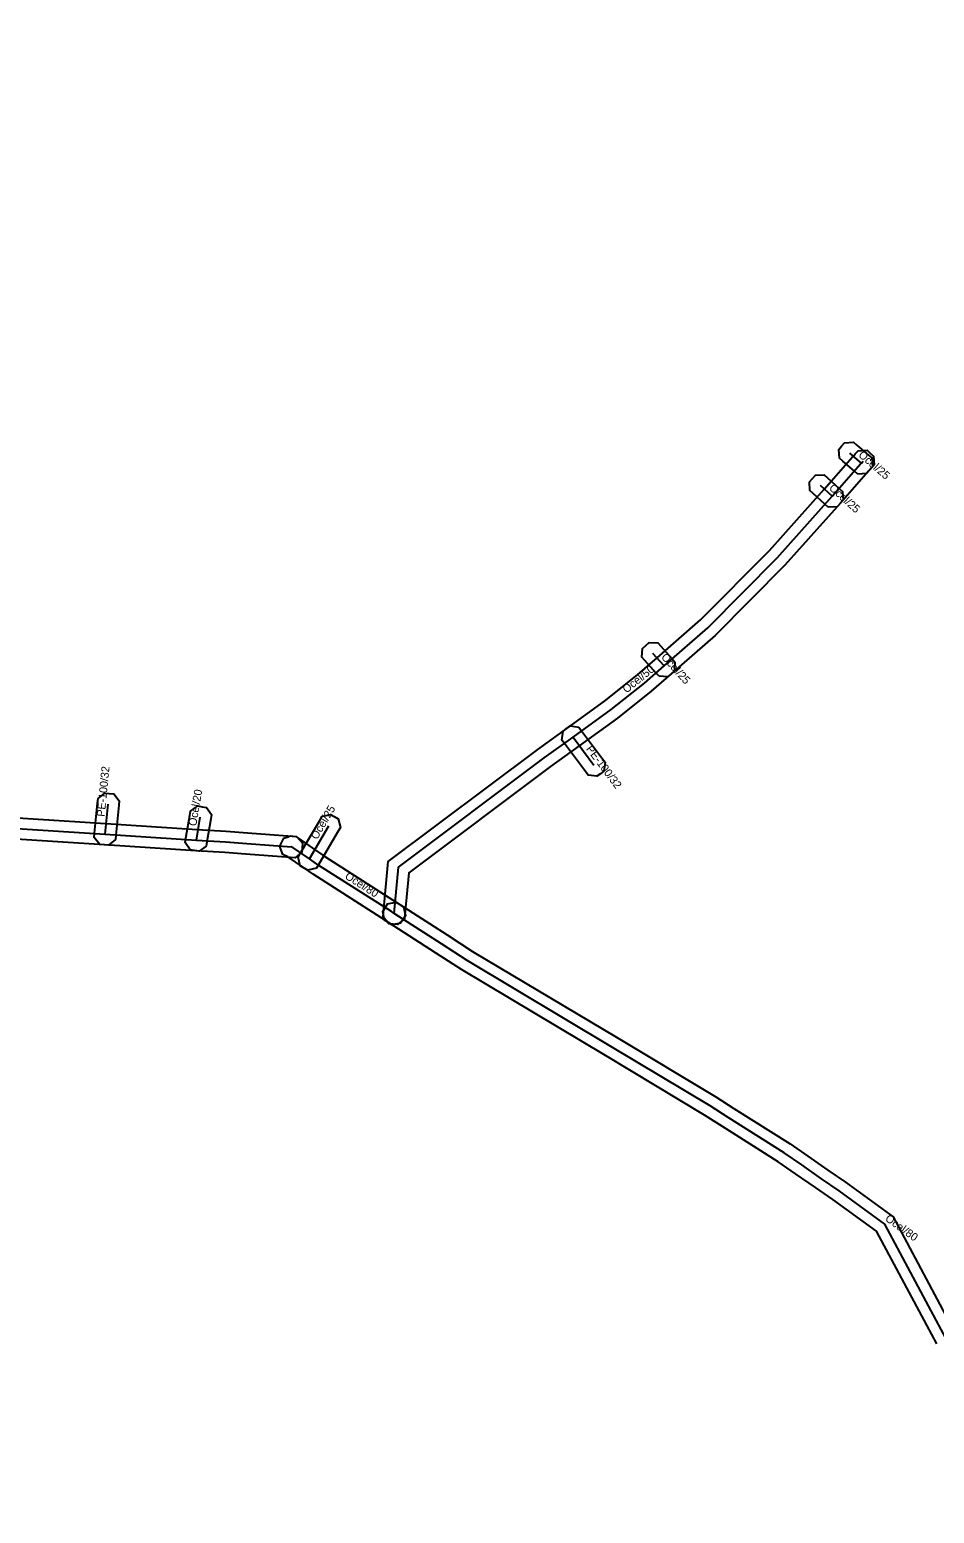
# Model space of a CAD drawing. Extents: x -569373 to -565022, y -1135090 to -1131496.
# Drawn here: x -565532.3 to -565447.5, y -1133985.7 to -1133846.6 of the extents above; entities that cross this region are included whole.
import ezdxf

# ---------------------------------------------------------------- set-up
doc = ezdxf.new("R2010")
doc.units = 0
for name, color, linetype in [('1', 7, 'Continuous'), ('24', 7, 'Continuous'), ('30', 7, 'Continuous')]:
    doc.layers.add(name, color=color, linetype=linetype)

msp = doc.modelspace()

# ---------------------------------------------------------------- linework, layer by layer
at = {"layer": '1'}
for points in [[(-565454.709, -1133888.287), (-565455.023, -1133888.017), (-565456.113, -1133887.077), (-565456.427, -1133886.807), (-565456.487, -1133885.981), (-565456.217, -1133885.667), (-565455.947, -1133885.353), (-565455.121, -1133885.293), (-565454.807, -1133885.563), (-565453.717, -1133886.503), (-565453.403, -1133886.773), (-565453.343, -1133887.599), (-565453.613, -1133887.913), (-565453.883, -1133888.227)], [(-565499.175, -1133929.779), (-565499.136, -1133929.366), (-565498.684, -1133924.585), (-565484.663, -1133914.085), (-565481.967, -1133912.13), (-565478.425, -1133909.563), (-565475.331, -1133907.102), (-565473.509, -1133905.507), (-565469.445, -1133901.951), (-565462.988, -1133895.444), (-565457.857, -1133889.705), (-565457.17, -1133888.928), (-565455.192, -1133886.68), (-565455.119, -1133886.597), (-565454.945, -1133886.403), (-565454.669, -1133886.094), (-565453.842, -1133886.049), (-565453.533, -1133886.325), (-565453.224, -1133886.601), (-565453.179, -1133887.428), (-565453.455, -1133887.737), (-565453.621, -1133887.923), (-565453.688, -1133888), (-565455.67, -1133890.252), (-565456.363, -1133891.035), (-565461.532, -1133896.816), (-565468.075, -1133903.409), (-565472.191, -1133907.013), (-565474.049, -1133908.638), (-565477.215, -1133911.157), (-565480.793, -1133913.75), (-565483.477, -1133915.695), (-565496.776, -1133925.655), (-565497.144, -1133929.554), (-565497.183, -1133929.967), (-565497.821, -1133930.495), (-565498.234, -1133930.456), (-565498.647, -1133930.417)], [(-565457.476, -1133891.389), (-565457.783, -1133891.11), (-565458.883, -1133890.11), (-565459.19, -1133889.831), (-565459.229, -1133889.004), (-565458.95, -1133888.697), (-565458.671, -1133888.39), (-565457.844, -1133888.351), (-565457.537, -1133888.63), (-565456.437, -1133889.63), (-565456.13, -1133889.909), (-565456.091, -1133890.736), (-565456.37, -1133891.043), (-565456.649, -1133891.35)], [(-565473.317, -1133907.236), (-565473.594, -1133906.928), (-565474.644, -1133905.758), (-565474.921, -1133905.45), (-565474.876, -1133904.623), (-565474.568, -1133904.346), (-565474.26, -1133904.069), (-565473.433, -1133904.114), (-565473.156, -1133904.422), (-565472.106, -1133905.592), (-565471.829, -1133905.9), (-565471.874, -1133906.727), (-565472.182, -1133907.004), (-565472.49, -1133907.281)], [(-565480.827, -1133912.009), (-565480.579, -1133912.341), (-565478.619, -1133914.961), (-565478.371, -1133915.293), (-565478.489, -1133916.113), (-565478.821, -1133916.361), (-565479.153, -1133916.609), (-565479.973, -1133916.491), (-565480.221, -1133916.159), (-565482.181, -1133913.539), (-565482.429, -1133913.207), (-565482.311, -1133912.387), (-565481.979, -1133912.139), (-565481.647, -1133911.891)], [(-565526.236, -1133922.343), (-565526.195, -1133921.931), (-565525.915, -1133919.111), (-565525.874, -1133918.699), (-565525.233, -1133918.174), (-565524.821, -1133918.215), (-565524.409, -1133918.256), (-565523.884, -1133918.897), (-565523.925, -1133919.309), (-565524.205, -1133922.129), (-565524.246, -1133922.541), (-565524.887, -1133923.066), (-565525.299, -1133923.025), (-565525.711, -1133922.984)], [(-565517.715, -1133922.822), (-565517.646, -1133922.414), (-565517.286, -1133920.274), (-565517.217, -1133919.866), (-565516.542, -1133919.385), (-565516.134, -1133919.454), (-565515.726, -1133919.523), (-565515.245, -1133920.198), (-565515.314, -1133920.606), (-565515.674, -1133922.746), (-565515.743, -1133923.154), (-565516.418, -1133923.635), (-565516.826, -1133923.566), (-565517.234, -1133923.497)], [(-565507.142, -1133924.189), (-565506.932, -1133923.832), (-565505.112, -1133920.742), (-565504.902, -1133920.385), (-565504.099, -1133920.178), (-565503.742, -1133920.388), (-565503.385, -1133920.598), (-565503.178, -1133921.401), (-565503.388, -1133921.758), (-565505.208, -1133924.848), (-565505.418, -1133925.205), (-565506.221, -1133925.412), (-565506.578, -1133925.202), (-565506.935, -1133924.992)], [(-565506.637, -1133925.164), (-565508.1, -1133924.168), (-565508.578, -1133923.929), (-565508.709, -1133923.536), (-565508.84, -1133923.143), (-565508.469, -1133922.402), (-565508.076, -1133922.271), (-565508.046, -1133922.261), (-565507.824, -1133922.187), (-565507.361, -1133922.252), (-565507.167, -1133922.383), (-565505.503, -1133923.516), (-565504.625, -1133924.128), (-565497.857, -1133928.45), (-565497.593, -1133928.623), (-565497.246, -1133928.85), (-565497.076, -1133929.66), (-565497.303, -1133930.007), (-565497.53, -1133930.354), (-565498.34, -1133930.524), (-565498.687, -1133930.297), (-565498.943, -1133930.13), (-565505.735, -1133925.792)]]:
    msp.add_lwpolyline(points, close=True, dxfattribs=at)
for points in [[(-565534.394, -1133920.442), (-565525.136, -1133921.032), (-565516.597, -1133921.582), (-565513.861, -1133921.752), (-565511.864, -1133921.903), (-565507.684, -1133922.223), (-565507.271, -1133922.254), (-565506.732, -1133922.883), (-565506.763, -1133923.296), (-565506.794, -1133923.709), (-565507.423, -1133924.248), (-565507.836, -1133924.217), (-565512.016, -1133923.897), (-565513.999, -1133923.748), (-565516.723, -1133923.578), (-565525.264, -1133923.028), (-565534.506, -1133922.438)], [(-565447.317, -1133969.783), (-565448.252, -1133968.031), (-565452.954, -1133959.234), (-565457.029, -1133956.276), (-565458.661, -1133955.144), (-565460.528, -1133953.85), (-565462.153, -1133952.724), (-565467.375, -1133949.415), (-565469.055, -1133948.351), (-565478.344, -1133942.778), (-565491.837, -1133934.71), (-565494.257, -1133933.152), (-565498.682, -1133930.301), (-565499.03, -1133930.076), (-565499.205, -1133929.266), (-565498.981, -1133928.918), (-565498.756, -1133928.57), (-565497.946, -1133928.395), (-565497.598, -1133928.619), (-565493.173, -1133931.47), (-565490.783, -1133933.01), (-565477.316, -1133941.062), (-565468.005, -1133946.649), (-565466.305, -1133947.725), (-565461.047, -1133951.056), (-565459.388, -1133952.206), (-565457.521, -1133953.5), (-565455.871, -1133954.644), (-565451.406, -1133957.886), (-565446.488, -1133967.089)]]:
    msp.add_lwpolyline(points, dxfattribs=at)
at = {"layer": '24'}
for points in [[(-565579.49, -1133846.01), (-565580.85, -1133848.22), (-565588.2, -1133860.18), (-565592.04, -1133865.81), (-565595.63, -1133871.07), (-565584.05, -1133886.37), (-565583.94, -1133886.52), (-565582.13, -1133888.95), (-565569.79, -1133905.24), (-565569.78, -1133905.26), (-565568.53, -1133906.82), (-565568.34, -1133907.04), (-565564.3, -1133909.45), (-565562.562, -1133910.433), (-565555.42, -1133914.47), (-565549.74, -1133917.67), (-565539.06, -1133921.22), (-565536.45, -1133921.345), (-565534.45, -1133921.44), (-565525.2, -1133922.03), (-565516.66, -1133922.58), (-565513.93, -1133922.75), (-565511.94, -1133922.9), (-565507.76, -1133923.22)], [(-565454.37, -1133887.26), (-565455.46, -1133886.32)], [(-565498.14, -1133929.46), (-565497.73, -1133925.12), (-565484.07, -1133914.89), (-565481.38, -1133912.94), (-565477.82, -1133910.36), (-565474.69, -1133907.87), (-565472.85, -1133906.26), (-565468.76, -1133902.68), (-565462.26, -1133896.13), (-565457.11, -1133890.37), (-565456.42, -1133889.59), (-565454.44, -1133887.34), (-565454.37, -1133887.26), (-565454.2, -1133887.07)], [(-565457.11, -1133890.37), (-565458.21, -1133889.37)], [(-565472.85, -1133906.26), (-565473.9, -1133905.09)], [(-565481.38, -1133912.94), (-565479.42, -1133915.56)], [(-565525.2, -1133922.03), (-565524.92, -1133919.21)], [(-565516.66, -1133922.58), (-565516.3, -1133920.44)], [(-565506.07, -1133924.34), (-565504.25, -1133921.25)], [(-565498.14, -1133929.46), (-565498.4, -1133929.29), (-565505.18, -1133924.96), (-565506.07, -1133924.34), (-565507.73, -1133923.21), (-565507.76, -1133923.22)], [(-565420.63, -1134001.3), (-565421.33, -1134000.81), (-565421.78, -1134000.41), (-565427.03, -1133995.78), (-565429.48, -1133993.62), (-565437.46, -1133986.27), (-565438.59, -1133984.27), (-565440.77, -1133980.42), (-565446.43, -1133969.32), (-565447.37, -1133967.56), (-565452.18, -1133958.56), (-565456.45, -1133955.46), (-565458.091, -1133954.322), (-565459.958, -1133953.028), (-565461.6, -1133951.89), (-565466.84, -1133948.57), (-565468.53, -1133947.5), (-565477.83, -1133941.92), (-565491.31, -1133933.86), (-565493.715, -1133932.311), (-565498.14, -1133929.46)]]:
    msp.add_lwpolyline(points, dxfattribs=at)

# ---------------------------------------------------------------- texts
at = {"layer": '30'}
for s, rotation, p in [('Ocel/25', 319.226, (-565454.715, -1133886.59)), ('Ocel/25', 317.72631, (-565457.46, -1133889.67)), ('Ocel/25', 311.90594, (-565473.175, -1133905.475)), ('Ocel/50', 38.5032, (-565476.381, -1133908.856)), ('PE-100/32', 306.79985, (-565480.2, -1133914.05)), ('PE-100/32', 84.32964, (-565525.26, -1133920.42)), ('Ocel/20', 80.45087, (-565516.68, -1133921.31)), ('Ocel/25', 59.50205, (-565505.36, -1133922.595)), ('Ocel/80', 327.43595, (-565502.818, -1133926.141)), ('Ocel/80', 324.02053, (-565452.21, -1133958.193))]:
    msp.add_text(s, height=0.75, rotation=rotation, dxfattribs=at).set_placement(p)

doc.saveas('drawing.dxf')
